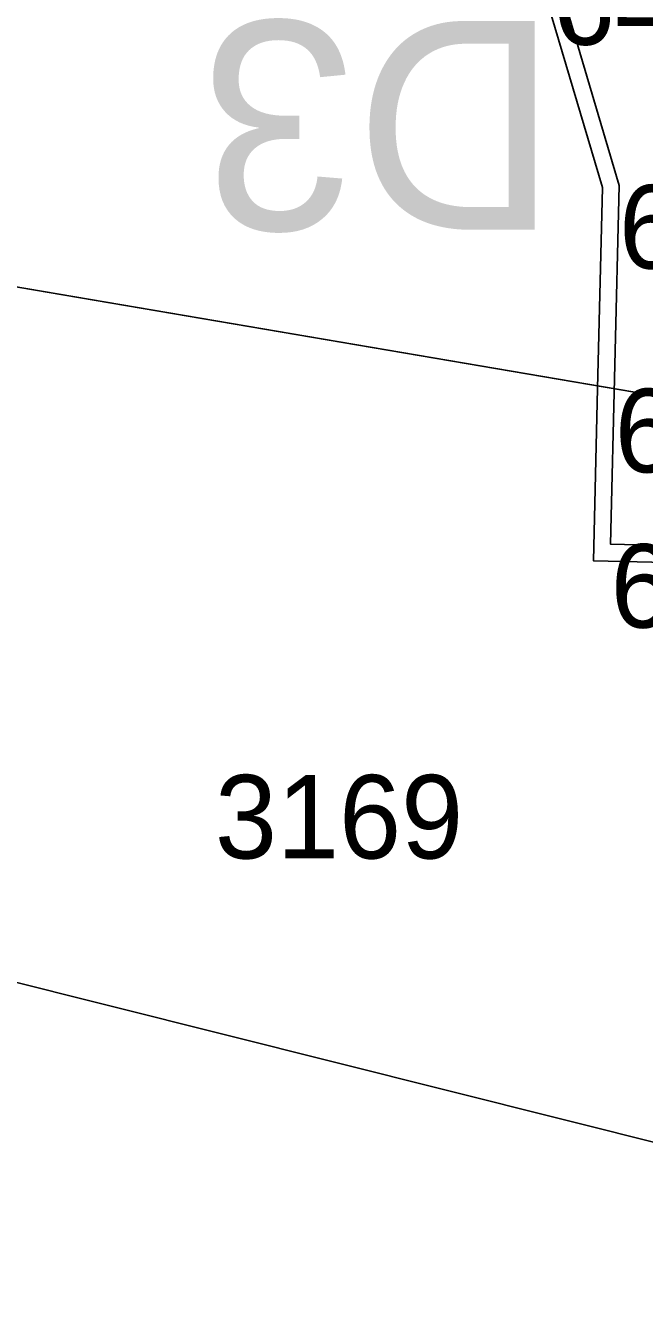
# Model space of a CAD drawing. Extents: x -728800 to -728100, y -1073200 to -1072700.
# Drawn here: x -728528.4 to -728520.98, y -1073041.72 to -1073026.38 of the extents above; entities that cross this region are included whole.
import ezdxf

# ---------------------------------------------------------------- set-up
doc = ezdxf.new("R2010")
doc.units = 0
for name, color, linetype in [('A1_OBVOD Spravy železnic', 7, 'Continuous'), ('A2_OBVOD STAVBY', 7, 'Continuous'), ('B1_body_poloha', 7, 'Continuous'), ('B2_body_číslo', 7, 'Continuous'), ('B6_JŽM', 7, 'Continuous'), ('K_01_Hranice parcel', 7, 'Continuous'), ('K_02_Parcelní čísla', 7, 'Continuous'), ('ZA_02_Dočasný_do_1_roku', 7, 'Continuous')]:
    doc.layers.add(name, color=color, linetype=linetype)

msp = doc.modelspace()

# ---------------------------------------------------------------- linework, layer by layer
at = {"layer": 'A1_OBVOD Spravy železnic'}
msp.add_lwpolyline([(-728604.14, -1072988.92), (-728582.13, -1073004.22), (-728556.03, -1073020.59), (-728543.86, -1073026.9), (-728510.71, -1073032.54), (-728510.22, -1073036.28), (-728509.42, -1073042.19), (-728509.9, -1073046.86), (-728541.12, -1073039.22), (-728572.55, -1073027.78), (-728581.66, -1073022.5), (-728594.83, -1073014.86), (-728598.74, -1073012.6)], dxfattribs=at)
at = {"layer": 'A2_OBVOD STAVBY'}
msp.add_lwpolyline([(-728556.425, -1073019.431), (-728548.14, -1073022.833), (-728542.882, -1073024.621), (-728538.694, -1073025.349), (-728534.14, -1073025.737), (-728532.664, -1073025.787), (-728522.232, -1073025.806), (-728521.488, -1073028.32), (-728521.545, -1073030.726), (-728521.594, -1073032.788), (-728517.755, -1073032.879), (-728517.209, -1073045.129)], dxfattribs=at)
at = {"layer": 'B1_body_poloha'}
for p, q in [((-728521.29, -1073028.29), (-728521.29, -1073028.29)), ((-728521.34, -1073030.73), (-728521.34, -1073030.73)), ((-728521.39, -1073032.59), (-728521.39, -1073032.59))]:
    msp.add_line(p, q, dxfattribs=at)
at = {"layer": 'B6_JŽM'}
msp.add_lwpolyline([(-728300.809, -1073024.355), (-728320.8, -1073026.914), (-728374.008, -1073033.722), (-728429.095, -1073040.747), (-728461.932, -1073044.273), (-728481.199, -1073044.815), (-728499.353, -1073043.648), (-728506.01, -1073042.737), (-728514.574, -1073041.329), (-728535.848, -1073035.998), (-728561.353, -1073026.113), (-728583.963, -1073013.524), (-728603.757, -1072998.891), (-728619.185, -1072984.418), (-728634.193, -1072966.825), (-728646.078, -1072949.194), (-728656.182, -1072930.072), (-728664.987, -1072910.227), (-728668.627, -1072901.808), (-728681.252, -1072876.016), (-728691.886, -1072859.663)], dxfattribs=at)
at = {"layer": 'K_01_Hranice parcel'}
msp.add_lwpolyline([(-728564.68, -1073020.02), (-728543.86, -1073026.9), (-728514.39, -1073031.91)], dxfattribs=at)
at = {"layer": 'ZA_02_Dočasný_do_1_roku'}
msp.add_lwpolyline([(-728531.162, -1073023.637), (-728526.817, -1073023.623), (-728522.471, -1073023.608), (-728519.714, -1073021.793), (-728519.139, -1073021.757), (-728517.575, -1073020.827), (-728516.889, -1073019.476), (-728516.969, -1073018.905), (-728513.177, -1073020.424), (-728512.181, -1073020.241), (-728512.132, -1073022.73), (-728509.606, -1073035.517), (-728510.327, -1073035.465), (-728509.415, -1073042.185), (-728509.9, -1073046.86), (-728517.01, -1073045.12), (-728517.286, -1073038.902), (-728517.563, -1073032.683), (-728521.389, -1073032.592), (-728521.287, -1073028.294), (-728522.083, -1073025.607), (-728532.66, -1073025.587)], dxfattribs=at)

# ---------------------------------------------------------------- texts
at = {"layer": 'B2_body_číslo'}
for s, p in [('64', (-728522.08, -1073026.61)), ('65', (-728521.29, -1073029.29)), ('66', (-728521.34, -1073031.73)), ('67', (-728521.39, -1073033.59))]:
    msp.add_text(s, height=1, dxfattribs=at).set_placement(p)
at = {"layer": 'K_02_Parcelní čísla'}
msp.add_text('3169', height=1, dxfattribs=at).set_placement((-728526.13, -1073036.354))
at = {"layer": 'ZA_02_Dočasný_do_1_roku'}
msp.add_text('D3', height=2.5, rotation=180, dxfattribs=at).set_placement((-728522.024, -1073026.326))

doc.saveas('drawing.dxf')
